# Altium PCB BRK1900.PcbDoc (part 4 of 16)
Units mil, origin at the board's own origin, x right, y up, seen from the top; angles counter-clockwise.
Board outline 8858.27 x 5905.51 mil, 10 copper layers (L1-TOP, L2-GND, L3-PWR, L4-GND, L5-PWR, L6-PWR, L7-GND, L8-SIG, L9-GND, L10-BOT), stack 48.824 mil thick; 456 components, 571 nets, 2296 pads, 2416 vias.
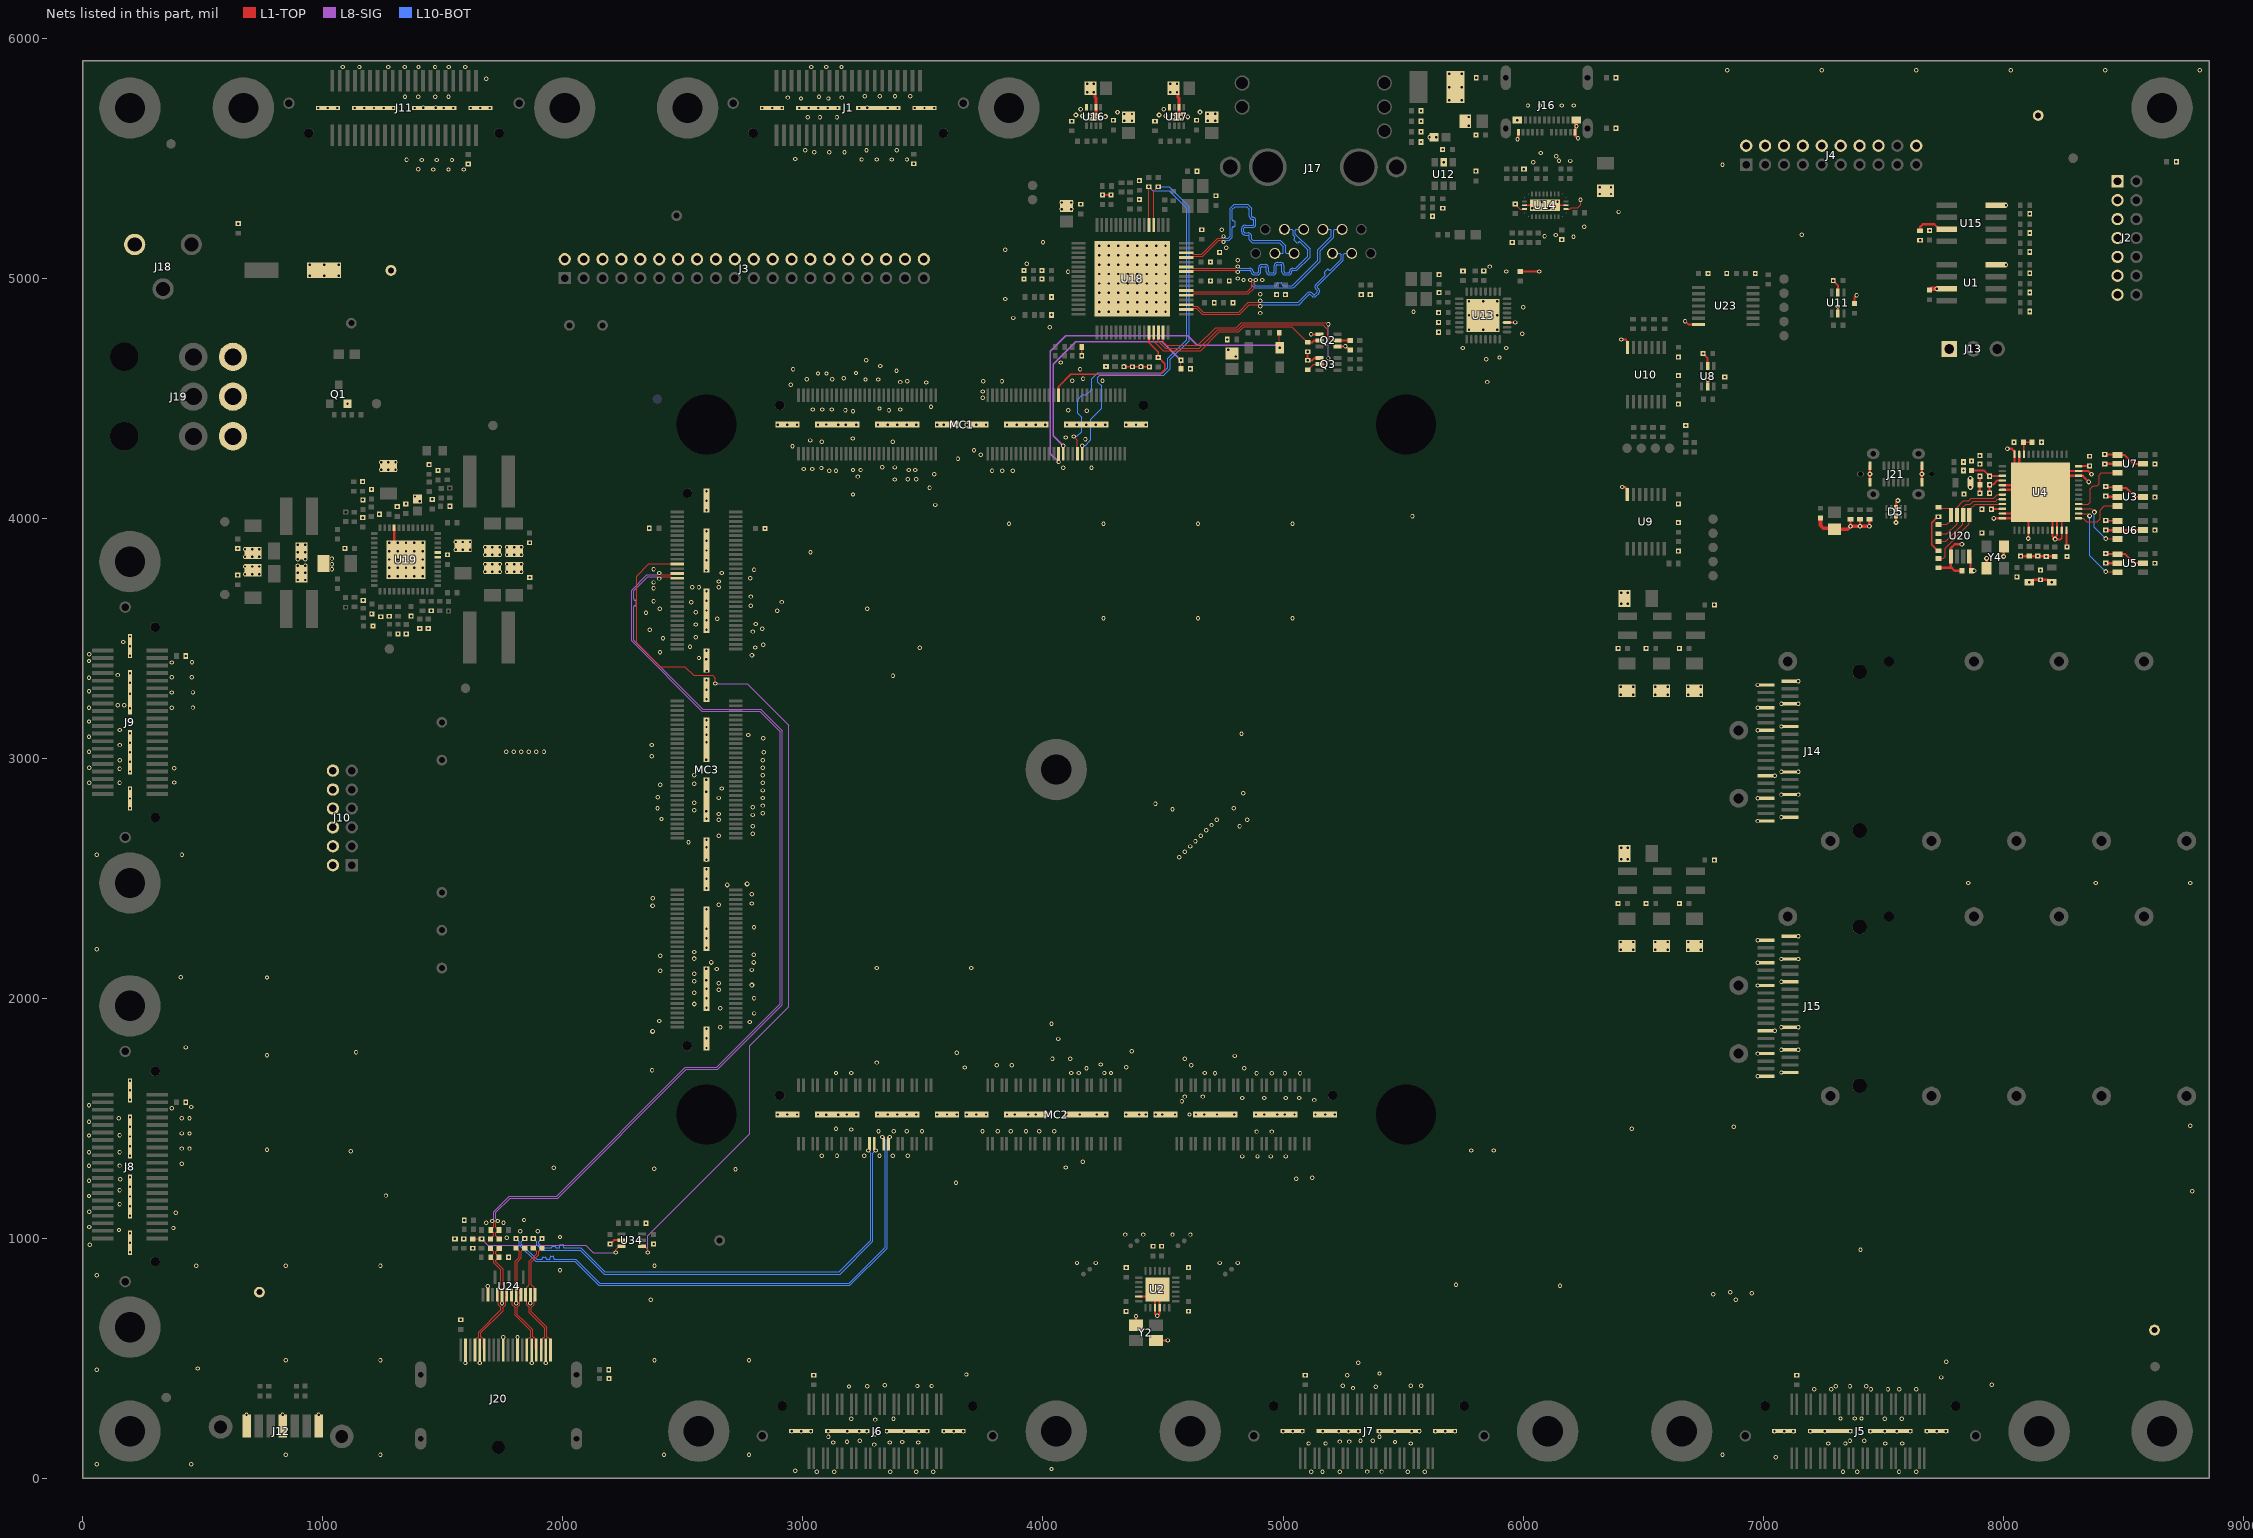
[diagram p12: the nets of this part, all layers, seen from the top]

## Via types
v1: diameter 18, hole 10, L1-TOP to L10-BOT, tented both sides, 2170 vias
v2: diameter 20, hole 10, L1-TOP to L10-BOT, tented both sides, 246 vias

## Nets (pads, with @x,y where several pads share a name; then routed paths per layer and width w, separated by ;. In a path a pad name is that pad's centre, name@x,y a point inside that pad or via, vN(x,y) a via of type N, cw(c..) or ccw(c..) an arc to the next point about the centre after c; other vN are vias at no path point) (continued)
DGND: C1.1 C2.1 C3.1 C4.1 C5.1 C6.1 C7.1 C8.1 C9.1 C10.1 C11.1 C12.1 C13.1 C14.1 C15.1 C16.1 C17.1 C18.1 C19.1 C20.2 C21.2 C22.1 C23.1 C28.1 C29.1 C30.1 C31.1 C32.1 C33.1 C34.1 C35.1 C36.1 C37.1 C38.1 C39.1 C40.1 C41.1 C42.1 C49.1 C50.1 C51.1 C52.1 C53.1 C54.1 C55.1 C56.1 C57.1 C58.1 C59.1 C60.1 C61.1 C62.1 C63.1 C64.1 C65.1 C66.1 C67.1 C68.1 C69.1 C70.1 C71.1 C72.1 C73.1 C74.1 C75.1 C76.1 C77.1 C78.1 C81.1 C82.1 C84.1 C85.1 C86.1 C88.1 C89.1 C90.1 C91.1 C92.1 C93.1 C94.1 C95.1 C96.1 C97.1 C98.1 C99.1 C100.1 C101.1 C102.1 C103.1 C104.1 C105.1 C106.1 C107.1 C108.1 C109.1 C110.1 C111.1 C112.1 C113.1 C114.1 C115.1 C116.2 C117.2 C119.1 C120.1 C121.1 C123.2 C124.2 C125.2 C127.2 C128.2 C129.1 C130.1 C131.1 C132.1 C134.2 C135.1 C136.2 C137.2 C138.2 C140.2 C141.2 C142.1 C143.1 C144.1 C146.2 C147.2 C148.2 C150.1 C151.1 C152.1 C155.2 C156.1 C157.2 C159.1 C163.1 C164.1 C168.2 C178.1 C179.1 C180.1 C181.1 C183.1 C184.1 C186.1 C188.1 C190.1 C212.1 C213.1 C214.2 C215.1 C218.1 C219.1 C220.1 C221.1 D5.3 D5.8 FB1.2 FB5.2 J1.0 J2.1 J2.3 J2.5 J2.7 J2.9 J2.11 J2.13 J3.2 J3.4 J3.6 J3.8 J3.10 J3.12 J3.14 J3.16 J3.18 J3.20 J3.22 J3.24 J3.26 J3.28 J3.30 J3.32 J3.34 J3.36 J3.38 J3.40 J4.2 J4.4 J4.6 J4.8 J4.10 J4.12 J4.14 J4.16 J4.20 J5.0 J6.0 J7.0 J8.0 J9.0 J10.2 J10.4 J10.6 J10.8 J10.10 J10.12 J11.0 J12.1 J12.4 J12.7 J13.1 J14.1 J14.4 J14.7 J14.13 J14.16 J14.19 J14.20 J14.23 J14.26 J14.32 J14.35 J14.38 J15.1 J15.4 J15.7 J15.13 J15.16 J15.19 J15.20 J15.23 J15.26 J15.32 J15.35 J15.38 J16.A1 J16.A12 J16.B1 J16.B12 J18.2 J19.4 J19.5 J19.6 J20.2 J20.5 J20.8 J20.11 J20.16 J20.19 J21.A1 J21.A12 J21.B1 J21.B12 MC1.0 MC2.0 MC3.0 Q1.2 Q2.1 Q2.4 Q3.1 R1.1 R5.1 R6.1 R7.1 R8.1 R11.1 R12.2 R13.1 R14.1 R15.1 R16.1 R17.1 R18.1 R19.2 R20.1 R22.2 R23.2 R24.2 R26.1 R59.1 R61.1 R66.1 R70.2 R73.2 R76.1 R77.2 R78.2 R79.2 R83.1 R87.1 R88.1 R89.1 R90.1 R91.1 R92.1 R93.1 R96.1 R103.1 R105.1 R106.1 R107.1 R108.1 R109.1 R110.1 R112.1 R118.1 R123.1 R126.1 R130.1 R131.2 R134.1 R135.1 R140.1 R152.1 R154.1 R155.1 R156.2 R157.2 R159.1 R169.1 R184.1 TP2.1 TP5.1 TP8.1 TP11.1 U1.4 U1.7 U2.3 U2.4 U2.23 U2.PAD U3.2 U4.4 U4.9 U4.10 U4.11 U4.22 U4.23 U4.35 U4.36 U4.41 U4.42 U4.47 U4.48 U4.PAD U5.2 U6.2 U6.5 U7.2 U8.2 U8.5 U9.7 U10.7 U11.2 U11.5 U12.2 U13.0 U13.11 U14.12 U14.13 U14.28 U14.29 U14.PAD U15.4 U16.2 U16.4 U16.EP U17.2 U17.4 U17.EP U18.PAD U19.7 U19.8 U19.21 U19.PAD U20.5 U23.7 U24.2 U24.5 U24.8 U24.11 U34.2 Y2.2 Y2.4 Y4.2 Y4.4 | length 5547.5
  L1-TOP w5: v1(5967.41,5308.4) 5968,5308.4 5975.74,5300.67 5975.74,5300.07 5988.31,5287.5 U14.29@6005.76,5287.5 ; U14.12@6178.99,5287.5 6194.5,5287.5 6201,5294 6227.22,5294 6239.22,5306 v1(6239.22,5326)
  L1-TOP w7: U13.11@5932.96,4814.94 5966.68,4814.94 v1(5967.02,4815.28)
  L1-TOP w7.5: U14.28@6005.76,5303.24 6091,5303.24 U14.PAD@6091.59,5303.83 6092.18,5303.24 U14.13@6178.99,5303.24
  L1-TOP w8: v1(2196.85,976.38) 2197.44,976.38 2213.58,992.52 U34.2@2244.09,992.52 ; v1(4161.42,4677.17) R92.1@4161.42,4712.6 ; v2(4248.09,5347.15) 4248.03,5347.1 C96.1@4248.03,5346.85 4258.56,5346.85 4258.86,5347.15 ; C96.1@4258.56,5347.15 C95.1@4283.12,5347.15 ; 4270.86,5347.15 4271.16,5346.85 C95.1@4283.46,5346.85 v2(4283.52,5346.76) ; C101.1@4337.21,4630.74 v2(4372.65,4630.74) C91.1@4408.08,4630.74 v2(4443.51,4630.74) ; Y2.2@4387.4,637.8 v1(4387.4,675.59) ; U2.23@4399.61,757.87 4446.85,757.87 U2.PAD@4466.54,777.56 ; Y2.4@4470.87,574.8 v1(4519.69,574.8) ; v1(5102.36,4692.91) v1(5102.36,4657.48) 5122.05,4657.48 5131.89,4667.32 Q3.1@5151.57,4667.32 ; v1(5116.72,4765.94) 5116.81,4765.84 5151.48,4765.84 Q2.1@5151.57,4765.75 ; Q2.4@5226.38,4714.57 5227.36,4715.55 5258.86,4715.55 v1(5259.84,4716.54) 5261.81,4716.54 5269.68,4708.66 5277.56,4700.79 R106.1@5279.53,4700.79 ; R12.2@5988.19,5027.56 v1(6066.93,5027.56) ; v1(6409.28,4744.36) 6426.94,4744.36 6431.62,4739.68 6431.62,4714.08 U10.7@6434.51,4711.19 ; v1(6674.57,4820.59) 6688.18,4806.98 U23.7@6730.74,4806.98 ; v1(6749.82,4685.95) 6749.82,4685.36 6768.9,4666.28 U8.2@6768.9,4634.26 ; U8.5@6768.9,4547.65 v1(6768.94,4575.51) ; v1(7291.94,4989.67) 7291.94,4989.08 7311.02,4970 U11.2@7311.02,4939.98 ; U11.5@7311.02,4853.36 v1(7311.02,4881.89) ; C66.1@7380.02,4893.75 7380.02,4919.67 v1(7389.02,4928.67) ; v2(8104.52,3915.4) 8105.57,3916.45 8105.57,3949.07 U4.4@8105.92,3949.42 U4.PAD@8105.92,4058.68 ; U4.PAD@8155.13,4107.89 U4.PAD@8204.35,4058.68 ; U2.PAD@4466.54,777.56 U2.PAD@4476.38,787.4 4486.22,777.56 U2.4@4486.22,710.63 4486.22,687.01 v1(4476.38,677.17) 4466.54,687.01 U2.3@4466.54,710.63 U2.PAD@4466.54,777.56 ; U4.PAD@8204.35,4058.68 U4.9@8204.35,3949.42 8204.35,3924.25 v2(8215.78,3912.82) ; U4.PAD@8204.35,4058.68 U4.PAD@8224.03,4038.99 ; v2(8215.78,3912.82) 8217.56,3911.04 8237.81,3911.04 8243.72,3916.94 U4.11@8243.72,3949.42 8243.72,4019.31 U4.PAD@8224.03,4038.99 ; v2(8215.78,3912.82) 8218.07,3915.12 8218.07,3923.16 8224.03,3929.12 U4.10@8224.03,3949.42 U4.PAD@8224.03,4038.99
  L1-TOP w10: v1(6413.39,4129.92) 6423.97,4129.92 6434.24,4119.65 U9.7@6434.24,4098.98 ; v2(7363.79,3966.16) R22.2@7363.79,3995.68 ; v2(7403.16,3966.16) R23.2@7403.16,3995.68 ; v2(7442.53,3966.16) R24.2@7442.53,3995.68 ; J21.A12@7444.5,4149.82 J21.B1@7444.5,4217.93 ; D5.8@7552.77,4010.15 7553.07,4009.86 7553.07,3982.26 v2(7553.36,3981.96) ; D5.3@7552.77,4040.17 7553.11,4040.52 7553.11,4062.63 7561.21,4070.73 v2(7561.21,4073.44) ; J21.A1@7661.04,4149.82 J21.B12@7661.04,4217.93 ; R26.1@7729.94,3792.93 7779.15,3792.93 7782.1,3795.88 ; v2(7827.63,3891.07) 7798.17,3891.07 7782.1,3875 U20.5@7782.1,3840.17 7782.1,3795.88 ; C41.1@7827.97,3781.12 7796.87,3781.12 7782.1,3795.88 ; v2(7902.77,4103.95) C22.1@7902.77,4139.39 v2(7902.77,4174.82) ; Y4.2@7929.74,3790.96 7930.72,3791.94 v2(7930.72,3832.3) ; v2(7960.59,3998.98) 7961.16,3999.54 7996.59,3999.54 U4.48@7996.67,3999.62 8046.87,3999.62 U4.PAD@8066.55,4019.31 ; U4.47@7996.67,4019.31 U4.PAD@8066.55,4019.31 ; U4.42@7996.67,4117.73 U4.PAD@8145.29,4117.73 ; U4.41@7996.67,4137.42 U4.PAD@8125.61,4137.42 ; v2(8001.59,3840.17) 8001.59,3880.53 Y4.4@8002.57,3881.51 ; v2(8017.34,4288.99) 8034.9,4288.99 8046.87,4277.02 U4.36@8046.87,4266.35 8046.87,4216.16 U4.PAD@8062.61,4200.41 ; U4.35@8066.55,4266.35 8066.55,4204.35 U4.PAD@8062.61,4200.41 ; v2(8072.46,3841.75) 8073.24,3840.96 8213.4,3840.96 C10.1@8214.19,3840.17 ; v2(8355.92,4151.2) 8330.33,4176.79 U4.22@8313.6,4176.79 U4.PAD@8224.03,4176.79 ; v2(8367.73,4182.69) 8353.95,4196.47 U4.23@8313.6,4196.47 8243.72,4196.47 U4.PAD@8224.03,4176.79 ; v2(8422.85,4225.61) 8423.05,4225.8 8475.8,4225.8 U7.2@8476,4226 ; v2(8426.79,3812.61) U5.2@8476,3812.61 ; v2(8426.79,3950.41) U6.2@8476,3950.41 U6.5@8582.3,3950.41 U6.5@8582.5,3950.21 ; v2(8426.79,4091.75) 8428.56,4089.98 8474.23,4089.98 U3.2@8476,4088.2 ; C34.1@8631.31,3950.21 v2(8631.51,3950.01) ; U4.PAD@8062.61,4200.41 U4.PAD@8125.61,4137.42 ; U4.PAD@8066.55,4019.31 8105.92,4058.68 U4.PAD@8155.13,4107.89 ; U4.PAD@8125.61,4137.42 U4.PAD@8145.29,4117.73 ; U4.PAD@8145.29,4117.73 U4.PAD@8155.13,4107.89 ; U4.PAD@8155.13,4107.89 U4.PAD@8224.03,4176.79
  L1-TOP w11: C157.2@1201.5,3601.56 C157.2@1204.58,3601.56 ; C146.2@1240.7,3589.45 v1(1241.29,3589.45) ; U19.21@1297.37,3959.53 1297.37,3876.85 v1(1346.58,3827.64) ; C156.1@1312.81,3518.08 v1(1313.4,3518.08) ; R134.1@1347.81,3517.87 v1(1348.4,3517.87) ; C124.2@1367.41,3591.92 v1(1368,3591.92) ; C125.2@1402.99,3540.48 v1(1403.58,3540.48) ; v1(5976.48,5578.02) 5980.31,5581.85 J16.A12@5980.31,5607.09 ; J16.A1@6216.17,5602.2 6216.17,5594.75 v1(6228.82,5582.1) ; J16.A1@6216.54,5607.09 6216.54,5654.33 J16.B12@6220.47,5658.27
  L1-TOP w12: U16.EP@4210.63,5672.83 4210.72,5672.83 4220.47,5682.58 U16.2@4220.47,5711.81 4220.47,5749.45 4216.44,5753.48 4216.44,5769.39 4212,5773.83 v2(4211.85,5773.83) ; U17.EP@4557.09,5672.44 4557.18,5672.44 4566.93,5682.19 4566.93,5749.06 4562.9,5753.09 4562.9,5768.99 C86.1@4558.46,5773.43
  L1-TOP w15: C36.1@7238.57,4001.2 7238.57,3970.09 7250.38,3958.28 7293.69,3958.28 FB5.2@7297.62,3954.35 7351.98,3954.35 v2(7363.79,3966.16) v2(7403.16,3966.16) v2(7442.53,3966.16)
  L1-TOP w18: C2.1@7693,4950.08 7693.59,4950.08 7699.51,4956 v1(7722.64,4956) U1.7@7764.64,4956 ; C94.1@7693,5198.08 C94.1@7693.59,5198.08
  L10-BOT w7: v1@1276.58,3754.66 v1(1276.58,3757.64)
  other v1: 3058.17,27.56 3129.92,27.56 3363.33,27.56 3471.55,27.56 3543.31,27.56 5118.11,27.56 5164.47,27.56 5236.22,27.56 5518.8,27.56 5590.55,27.56 7332.68,27.56 7391.73,27.56 7566.04,27.56 7637.8,27.56 5351.31,28.6 5410.36,28.6 2968.5,31.5 4035.43,39.37 59.06,59.06 452.76,59.06 7052.17,87.6 846.46,98.43 1240.16,98.43 2421.26,98.43 2775.59,98.43 6830.71,98.43 3297.61,140.99 5106.3,145.67 5177.17,145.67 5531.5,145.67 7271.65,145.67 7342.52,145.67 7507.87,145.67 7578.74,145.67 3125.98,149.61 3362.2,149.61 3480.32,149.61 3414.3,151.65 5466.33,151.82 3183.78,153.01 5236.22,153.54 5275.59,153.54 3236.22,157.48 5322.83,157.48 5374.02,157.48 7361.32,157.48 7420.37,157.48 3106.3,173.23 5401.57,173.23 3300.52,183.56 2952.88,196.85 2992.88,196.85 3032.88,196.85 3105.38,196.85 3185.38,196.85 3234.15,196.85 3265.38,196.85 3350,197 3421.26,196.85 3482,197 3515.38,196.85 3587.88,196.85 3627.88,196.85 3667.88,196.85 5000.13,196.85 5040.13,196.85 5080.13,196.85 5165.35,196.85 5232.63,196.85 5272.63,196.85 5312.63,196.85 5401.57,196.85 5464.57,196.85 5535.43,196.85 5568,197 5635.13,196.85 5675.13,196.85 5715.13,196.85 7047.24,196.85 7087.35,196.85 7125.98,196.85 7196.85,196.85 7255.91,196.85 7362.2,196.85 7446.85,196.85 7505.91,196.85 7557.09,196.85 7612.2,196.85 7682.28,196.85 7722.39,196.85 7761.02,196.85 3300.68,245.23 7506.99,248.03 7577.85,248.03 3200.94,249.1 3377.42,249.05 7321.95,249.61 7381,249.61 7409.45,249.61 682.48,265.5 832.48,265.5 982.48,265.5 7212.6,371.65 7283.46,371.65 7448.82,371.65 7519.69,371.65 7566.93,371.65 7637.8,371.65 5291.4,376.45 5385.83,381.89 3191.93,382.87 7302.26,383.46 7361.32,383.46 7429.13,383.46 3268.32,384.04 3477,385 3536,385 5248.03,385.83 5532,386.06 5576,386.06 3341,388 7952.76,389.76 2192.08,416 7742.22,420.71 5267.72,429.13 3045,429.69 5093,429.69 7140.24,429.69 3681.1,433.07 5401.57,437.01 59.06,452.76 2191.69,453 479.55,457.99 1594.28,480.95 1653.34,480.95 1869.87,480.95 1928.93,480.95 5312.64,481.56 7762.05,486.16 846.46,492.13 1240.16,492.13 2381.89,492.13 2775.59,492.13 1752.18,588.34 1811.23,588.34 1574.53,661.08 4346.46,696.46 4606.3,696.46 1746.72,729.96 1805.78,729.96 1864.83,729.96 2366.14,744.09 6885.83,744.09 6791.34,767.72 6952.76,771.65 6862.2,775.59 1687.67,800.04 6153.54,803.15 5720.47,807.09 59.06,846.46 1988.19,867.72 4346.46,877.95 4606.3,877.95 472.44,885.83 846.46,885.83 1240.16,885.83 2381.89,885.83 4141.73,897.64 4220.47,897.64 4736.22,897.64 4811.02,897.64 1773.9,922 196.85,941.71 7405.51,952.76 1624.53,958.31 4458.74,966.6 4494.18,966.99 28.71,973.62 2377.95,976.38 196.85,981.71 1550.53,997.69 1587.53,997.69 1766.53,1003 1988.19,1005.51 4342.52,1015.75 4417.32,1015.75 4539.37,1015.75 4614.17,1015.75 196.85,1021.71 1823.09,1029.08 1895.09,1029.08 151,1035 377.95,1043.31 27.05,1047.26 2346.46,1063.39 1681.1,1064.57 1752.95,1064.57 1588.84,1075 1838.58,1076.38 196.85,1094.21 387.2,1106.15 27.05,1110.26 196.85,1134.21 153.54,1141.73 196.85,1174.21 26.07,1176.41 1263.13,1178.3 8787.4,1196.85 153.54,1200.79 196.85,1214.21 3637.8,1232.28 26.07,1239.41 155.96,1246.87 5055.12,1248.03 5122.05,1251.97 196.85,1254.21 2719.41,1288.53 2381.35,1290.51 1961.7,1294.62 4094.49,1295.28 26.07,1302.41 153.54,1303.15 412.01,1311.07 4165.35,1318.9 4830.71,1341.34 4893.7,1341.34 4948.82,1341.34 5011.81,1341.34 196.85,1344.21 3078.74,1343.5 3141.73,1343.5 3255.91,1343.5 3318.9,1343.5 3374.02,1343.5 3437.01,1343.5 153.54,1358.27 26.07,1359.22 1117.13,1362.2 5783.46,1366.14 5877.95,1366.14 767.84,1369.07 412.01,1374.07 444.88,1374 196.85,1384.21 196.85,1424.21 26.07,1428.41 153.54,1429.13 412.01,1437.07 444.88,1437 4889.76,1444.88 4952.76,1444.88 3314.96,1445.67 3377.95,1445.67 3433.07,1445.67 3496.06,1445.67 3748.03,1445.67 3811.02,1445.67 3866.14,1445.67 3929.13,1445.67 3984.25,1445.67 4047.24,1445.67 3200.79,1453.59 3138,1456 6452.76,1456.69 196.85,1464.21 6877.95,1464.57 8779.53,1468.5 26.07,1485.22 149.61,1500 412.01,1500.07 444.88,1500 196.85,1504.21 3097,1515 3148,1515 2895.24,1515.75 2935.24,1515.75 2975.24,1515.75 3062.72,1515.75 3182.72,1515.75 3222.72,1515.75 3312.72,1515.75 3352.72,1515.75 3392.72,1515.75 3432.72,1515.75 3472.72,1515.75 3560.2,1515.75 3600.2,1515.75 3640.2,1515.75 3682.64,1515.75 3722.64,1515.75 3762.64,1515.75 3850.12,1515.75 3883,1516 3938,1516 3970.12,1515.75 4010.12,1515.75 4097,1516 4153.54,1515.75 4224.41,1515.75 4260.12,1515.75 4347.6,1515.75 4401.57,1515.75 4427.6,1515.75 4470.04,1515.75 4496.06,1515.75 4550.04,1515.75 4610.24,1515.75 4637.52,1515.75 4671,1516 4725,1516 4797.52,1515.75 4887.52,1515.75 4921,1516 4976,1516 5007.52,1515.75 5047.52,1515.75 5135,1515.75 5175,1515.75 5215,1515.75 371.18,1542.19 452.76,1547.24 26.07,1554.41 429.69,1567 4578.74,1570.87 5130,1576 196.85,1576.71 4830.71,1584.65 4921.26,1584.65 5011.81,1584.65 5066.93,1584.65 4590.55,1590.55 4665.35,1590.55 196.85,1616.71 196.85,1656.71 6977.14,1675.28 4716.54,1688.19 4889.76,1688.19 4952.76,1688.19 5007.87,1688.19 5070.87,1688.19 3137.8,1688.98 3200.79,1688.98 4118.11,1688.98 4149.61,1688.98 4255.91,1688.98 4283.46,1688.98 4673.23,1688.98 7075.96,1691.03 2371.64,1700.6 4181.1,1708.66 4838.58,1708.66 3674.21,1711.61 4346.46,1712.6 3807.09,1720.47 3870.08,1720.47 4618.11,1720.47 4240.16,1724.41 3307.09,1732.28 4039.37,1748.03 4114.17,1748.03 4590.55,1748.03 4799.21,1759.84 767.84,1762.77 6977.14,1769.77 3640.75,1773.62 1138.78,1775.59 4370.08,1779.53 7075.96,1785.52 7146.89,1785.52 2598.42,1792.87 429.13,1795.28 4062.99,1830.71 2598.42,1832.87 7048.07,1864.26 2598.42,1872.87 2655.37,1879.15 7075.96,1880.01 7146.89,1880.01 4035.43,1893.7 2778.67,1901.21 2401.57,1905.51 2796.57,1936.88 2656.13,1958.52 2598.42,1960.35 2598.42,2000.35 2796.57,2000.03 2547.24,2023.62 2598.42,2040.35 6977.14,2053.24 2649.61,2062.99 7075.96,2068.98 2598,2075 409,2087 767.72,2086.61 2547.24,2102.36 2405.51,2114.17 2787.4,2118.11 2641.73,2122.05 2598,2123 3307.09,2125.98 3700.79,2125.98 6977.14,2147.72 7075.96,2163.47 7146.89,2163.47 2405.51,2177.17 2795.28,2181.1 2547.24,2192.91 6407.07,2201.43 6459.07,2201.43 6549.79,2201.43 6601.79,2201.43 6688.57,2201.43 6740.57,2201.43 59.06,2204.72 2598.42,2210.35 6407.07,2234.35 6459.07,2234.35 6549.79,2234.35 6601.79,2234.35 6688.57,2234.35 6740.57,2234.35 6977.14,2242.21 2598.42,2250.35 7146.89,2257.96 2598.42,2290.35 2796.44,2295.95 2598.42,2370.35 2786.57,2394.67 6395.48,2395.04 6512.4,2394.68 6651.18,2394.68 2374.02,2417.32 2786.57,2434.04 2598.42,2457.83 7854.33,2480.32 8385.83,2480.32 8779.53,2480.32 2598.42,2497.83 2598.42,2537.83 6796.65,2575.79 2598.42,2577 6408.46,2579.72 6436.02,2579.72 4568.28,2587.97 59.06,2598.43 413.39,2598.43 4590.55,2610.24 6408.46,2626.97 6435.63,2626.97 2598.42,2629 4612.82,2632.51 2523.62,2649.61 4635.09,2654.78 2598.42,2660.28 2649.61,2677.17 4657.36,2677.05 2791.34,2685.04 4679.64,2699.32 2791.34,2716.54 4818.9,2716.54 4701.91,2721.59 6977.15,2738.29 2649.61,2744.09 4724.18,2743.86 4850.39,2744.09 2411,2746.73 2598.42,2747.76 7075.97,2754.04 2791.34,2763.78 2649.61,2767.72 2833.29,2771.34 2598,2779 2547.24,2783.46 4539.37,2787.4 2394.28,2791.31 4795.28,2791.34 196.85,2792.11 2791.34,2795.28 2833.29,2802.83 4468.5,2811.02 2547.24,2814.96 196.85,2832.11 6977.15,2832.78 2833.29,2834.33 2649.61,2834.65 2394.85,2837.88 7075.97,2848.53 7146.9,2848.53 4834.65,2854.33 2598,2861 2833.29,2865.83 196.85,2872.11 2661.42,2874.02 2405.51,2889.76 2547.24,2893.7 2833.29,2897.32 27.05,2897.66 153.54,2897.64 381.68,2899.01 2598,2910 7048.08,2927.27 2547.24,2929.13 2833.29,2928.82 7075.97,2943.02 7146.9,2943.02 196.85,2944.61 153.54,2956.69 381.62,2958.8 2833.29,2960.32 27.05,2960.66 196.85,2984.61 153.7,2991.71 2833.29,2991.81 2598,2994 2370.08,3007.87 196.85,3024.61 2837.27,3024.61 26.07,3026.81 1763.78,3027.56 1795.28,3027.56 1826.77,3027.56 1858.27,3027.56 1889.76,3027.56 1921.26,3027.56 153.7,3054.71 2370.08,3055.12 196.85,3064.61 2598.43,3066.93 2834.65,3082.68 26.07,3089.81 2772.16,3096.88 2598.43,3098.43 4826.77,3102.36 196.85,3104.61 6977.15,3116.24 153.7,3117.71 2598.43,3129.92 7075.97,3131.99 26.07,3152.81 2598.42,3157.76 196.85,3208.66 26.07,3209.61 370.31,3210.85 459.14,3211 6977.15,3210.73 145.67,3220.47 173.23,3220.47 7075.97,3226.48 7146.9,3226.48 2598.42,3245.24 6407.07,3264.43 6459.07,3264.43 6549.79,3264.43 6601.79,3264.43 6688.57,3264.43 6740.57,3264.43 197,3268 370.31,3273.85 459.14,3274 26.07,3278.81 2598.42,3285.24 6407.07,3297.35 6459.07,3297.35 6549.79,3297.35 6601.79,3297.35 6688.57,3297.35 6740.57,3297.35 6977.15,3305.22 196.85,3314.61 7146.9,3320.97 2598.42,3325.24 26.07,3335.61 370.6,3337.19 454.75,3336.87 3375,3344 145.67,3346.46 196.85,3354.61 2599,3363 370.48,3398.93 455.2,3400.18 26.07,3404.81 2598,3412 2566.93,3417.32 429.69,3426 196.85,3427.11 27.05,3433.16 2404.76,3441.02 2598.42,3447.68 6395.48,3458.03 6512.4,3457.68 6651.18,3457.68 3486.66,3459.72 2800.91,3461.42 2529.73,3464.47 196.85,3467.11 2834.65,3472.44 169.29,3484.25 2417.32,3500 2553.27,3503.94 196.85,3507.11 2791.34,3527.56 2362.2,3535.43 2598.42,3535.16 2830.71,3539.37 1439.66,3540.56 1209.24,3550.66 2553.27,3557.09 2803.15,3559.06 2598.42,3575.16 2643.58,3580.71 4251.97,3582.68 4645.67,3582.68 5039.37,3582.68 1277.29,3591.84 1203.04,3601.56 2346.46,3606.3 2553.27,3608.27 1451.58,3613.95 2893.7,3614.17 2598.42,3615.16 3267.72,3622.05 2404,3623 2783.25,3635.56 6796.65,3638.78 6408.46,3642.72 6436.02,3642.72 2534.86,3650.29 2911.36,3650.38 2377.95,3653.54 2598.42,3655.16 1169,3657.31 2783.25,3673.29 6408.46,3689.96 6435.63,3689.96 2598.42,3695.16 2377.95,3708.66 2539.37,3712.6 2566.93,3712.6 2649.61,3712.6 2377.95,3732.28 2649.61,3736.22 895.64,3742.42 927.81,3742.42 2780.35,3749.89 1862.58,3752.72 1311.58,3757.64 1346.58,3757.64 1381.58,3757.64 1416.58,3757.64 645.58,3762.8 676.18,3766.64 706.18,3766.64 735.88,3766.64 895.64,3772.42 927.81,3772.42 2661.42,3771.65 1676.58,3776.64 1706.58,3776.64 1736.58,3776.64 1767.58,3776.64 1797.58,3776.64 1827.58,3776.64 2597.63,3781.99 2796.57,3785.43 1038.11,3786.64 2377.95,3787.4 1276.58,3792.64 1311.58,3792.64 1346.58,3792.64 1381.58,3792.64 1416.58,3792.64 676.18,3798.81 706.18,3798.81 735.88,3798.81 895.64,3802.42 927.81,3802.42 1038.11,3808.64 1676.58,3808.81 1706.58,3808.81 1736.58,3808.81 1767.58,3808.81 1797.58,3808.81 1827.58,3808.81 2598.42,3825.16 1276.58,3827.64 1311.58,3827.64 1381.58,3827.64 1416.58,3827.64 895.36,3828.58 927.54,3828.58 1038.11,3831.64 676.18,3838.46 706.18,3838.46 735.88,3838.46 1676.58,3847.46 1706.58,3847.46 1736.58,3847.46 1767.58,3847.46 1797.58,3847.46 1827.58,3847.46 1519.58,3847.72 3031.5,3858.27 895.36,3858.58 927.54,3858.58 1276.58,3862.64 1311.58,3862.64 1346.58,3862.64 1381.58,3862.64 1416.58,3862.64 6646.94,3862.61 2598.42,3865.16 1553.58,3868.64 1583.58,3868.64 1613.58,3868.64 676.18,3870.64 706.18,3870.64 735.88,3870.64 645.58,3873.56 1091.92,3874 1676.58,3879.64 1706.58,3879.64 1736.58,3879.64 1767.58,3879.64 1797.58,3879.64 1827.58,3879.64 895.36,3888.58 927.54,3888.58 1276.58,3897.64 1311.58,3897.64 1346.58,3897.64 1381.58,3897.64 1416.58,3897.64 1861.58,3897.56 1553.58,3900.81 1583.58,3900.81 1613.58,3900.81 2598.42,3905.16 2598.42,3945.16 2842.16,3957 2359.92,3958 3858.27,3976.38 4251.97,3976.38 4645.67,3976.38 5039.37,3976.38 6646.94,3981.5 1166,4002.37 5539,4008.08 1235.92,4016 2598.42,4032.64 1310.58,4047.72 1529.69,4049 3551.18,4055.12 6646.94,4059.46 1346.58,4059.72 1404,4071 2598.42,4072.64 1167,4076.08 1456,4078.08 1384,4090 3208.66,4098.43 2598.42,4112.06 1203,4120.08 3527.56,4125.98 1166,4152.08 3383.18,4160.87 3437.01,4161.42 3472.44,4161.42 3228.35,4173.23 3547.33,4182.7 3110.24,4196.85 3137.8,4196.85 3788,4197 3831,4197 3874.02,4196.85 1480,4199.08 1243,4201 1273,4201 1303,4201 3208.66,4200.79 3240.16,4200.79 3440.94,4200.79 3468.5,4200.79 3003.94,4204.72 3039.37,4204.72 3077.11,4208.75 4085,4210 4202,4210 3382.89,4211.23 3330.53,4211.61 1443,4223.08 1243,4233.17 1273,4233.17 1303,4233.17 3645.67,4248.03 3740.16,4263.78 3712.6,4283.46 2956.69,4299.21 3078.74,4318.9 3374.02,4318.9 3030,4323.74 4176.89,4329.26 3207,4332 4095,4336 6677.17,4385.83 3147,4389 3178,4389 2895.24,4389.76 2935.24,4389.76 2975.24,4389.76 3062.72,4389.76 3097,4390 3222.72,4389.76 3312.72,4389.76 3352.72,4389.76 3392.72,4389.76 3432.72,4389.76 3472.72,4389.76 3560.2,4389.76 3586.61,4389.76 3640.2,4389.76 3682.64,4389.76 3722.64,4389.76 3762.64,4389.76 3850.12,4389.76 3890.12,4389.76 3930.12,4389.76 3970.12,4389.76 4010.12,4389.76 4100.12,4389.76 4140.12,4389.76 4180.12,4389.76 4220.12,4389.76 4260.12,4389.76 4347.6,4389.76 4387.6,4389.76 4427.6,4389.76 3208.66,4444.88 4183,4448 3177.17,4448.82 3358.27,4448.82 4105,4449 3041.19,4452.76 3080.71,4452.76 3120.08,4452.76 3405.51,4452.76 3318.9,4456.69 3533.64,4464.37 6646.59,4474.18 1103.1,4477.3 3749,4502 3749,4527.56 2948.82,4555.12 3514.36,4565.07 3405.51,4566.93 5850.39,4566.93 3751,4570 3829,4570 3435.04,4570.87 4122,4573 4248,4573 3260.9,4577.76 3313.9,4577.76 3015.75,4578.74 3122.05,4578.74 4167,4581 3170.08,4582.66 6839.9,4588.03 6646.59,4593.08 3062.99,4602.36 3098.43,4602.36 3221.27,4604.61 3389.76,4614.17 2959,4619.81 4154.54,4620.06 4614.17,4622.05 3322.83,4633.86 4074.1,4648.32 3263.78,4657.48 5846.46,4661.42 5901.57,4669.29 6646.59,4671.03 4803.15,4673.23 4771.65,4700.79 5748.03,4708.66 5929.13,4708.66 4767.72,4744.09 5996.06,4767.72 5647.94,4774.28 5774.5,4785.41 5833.55,4785.41 5892.61,4785.41 4027.56,4795.28 5647.94,4815.28 3876.18,4833.98 5774.5,4844.46 5833.55,4844.46 5892.61,4844.46 4035.43,4846.46 4905.51,4854.33 5647.94,4856.28 5543.61,4859.16 8110.69,4861 6000,4877.95 4791.73,4897.64 5774.5,4903.52 5833.55,4903.52 5892.61,4903.52 3842.44,4912.87 4035.43,4921.26 4973,4930.92 5010,4930.92 5326,4930.92 5363,4930.92 4905.51,4933.07 5650.02,4939.35 8110.69,4940 4775.98,4988.19 4835.29,4992.18 4913.39,4992.13 3920.87,4996.06 3995.67,4996.06 4811.32,4998.24 945.91,5010 1005.91,5010 1065.91,5010 5650.02,5014.35 6770.9,5019.06 6967.75,5019.06 6848.22,5019.68 8110.69,5020 4104.53,5026.35 5929.13,5027.56 5749.61,5029.09 5836.02,5030.35 3920.87,5031.5 3995.67,5031.5 5860.99,5047.99 945.91,5056 1005.91,5056 1065.91,5056 8011.36,5056 3933.07,5059.06 4811.02,5074.8 4735.83,5107.09 8110.69,5109 3842.52,5118.11 4763.78,5125.98 5954.41,5148.64 4000,5149.61 7653.54,5157.48 6161.35,5159.92 6210,5172 6089.36,5174.88 6136.01,5179.65 7161,5181 8110.69,5188 7693.3,5198.08 4661.42,5200.79 4744.09,5200.79 6255,5214 648,5227.08 5622.69,5257 8110.69,5268 6397.64,5275.59 6038.41,5290.32 6108.41,5290.32 5665.35,5291.34 8011.36,5304 4157.48,5307.48 6075.41,5317.32 6143.41,5317.32 4401.57,5327.17 4720.47,5342.91 6318.9,5350.39 6366.14,5350.39 6318.9,5377.95 6366.14,5377.95 4401.57,5405.91 5803.15,5445.28 1460.64,5452.39 1523.64,5452.39 1586.64,5452.39 1397.64,5452.76 6003.41,5454.01 6830.71,5472.44 1606,5475.31 3462,5476.31 5669.29,5482.28 6042,5482 8720.87,5484.25 6149.61,5488.19 6197,5488 1412,5492 1475,5492 1538,5492 1349,5493 3244.39,5494.14 3307.39,5494.14 3370.39,5494.14 3433.39,5494.14 2968.5,5496.06 6137.8,5507.87 6074,5521 3047.24,5523.62 3110.24,5523.62 3173.23,5523.62 3265,5532 3391,5532 3010,5533 5664.96,5535.43 5574.8,5566.93 5610.24,5586.61 5637.8,5586.61 5803.92,5596 5574.8,5610.24 6386.69,5624 6222.48,5633.1 5773,5635 5574.8,5653.54 5976.38,5658.27 3019.69,5669.29 3070.87,5669.29 3141.73,5669.29 5773,5671 4196.85,5673.23 4228.35,5673.23 4543.31,5672.83 4574.8,5672.83 5574.8,5696.85 981.08,5708.66 1021.08,5708.66 1061.08,5708.66 1133.58,5708.66 1173.58,5708.66 1213.58,5708.66 1253.58,5708.66 1293.58,5708.66 1383.58,5708.66 1418,5709 1470,5709 1503.58,5708.66 1543.58,5708.66 1616.08,5708.66 1656.08,5708.66 1696.08,5708.66 2831.48,5708.66 2871.48,5708.66 2911.48,5708.66 2983.98,5708.66 3023.98,5708.66 3063.98,5708.66 3103.98,5708.66 3143.98,5708.66 3233.98,5708.66 3268,5709 3353.98,5708.66 3393.98,5708.66 3466.48,5708.66 3506.48,5708.66 3546.48,5708.66 6020,5719 6070,5719 6161,5719 6211,5719 5692.91,5740.16 5744.09,5740.16 2992.13,5748.03 3106.3,5748.03 2937.01,5751.97 3161.42,5751.97 1342.52,5755.91 1397.75,5755.91 1468.52,5755.91 1523.75,5755.91 3066.93,5755.91 3257.62,5757.52 3320.62,5757.52 3383.62,5757.52 3446.62,5757.52 5692.91,5795.28 5744.09,5795.28 1681.1,5830.71 5804.31,5834 6386.69,5834 5692.91,5850.39 5744.09,5850.39 6850.39,5866.14 7244.09,5866.14 7637.8,5866.14 8031.5,5866.14 8425.2,5866.14 8818.9,5866.14 1083.59,5879.44 1152.78,5879.44 1272.59,5879.44 1341.78,5879.44 1398.59,5879.44 1467.78,5879.44 1524.59,5879.44 1593.78,5879.44 3034.68,5879.44 3097.68,5879.44 3160.68,5879.44
  other v2: 2374.02,1862.2 2547.24,1976.38 2649.61,2035.43 2787.4,2055.12 2547.24,2070.87 2618.11,2149.61 2795.28,2149.61 2547.24,2165.35 2374.02,2385.83 2649.61,2389.76 2685.04,2472.44 2767.72,2476.38 2787.4,3429.13 8056.71,3755.13 8155.13,3783.48 8631.51,3812.22 8178.76,3840.17 8265.37,3840.17 8143.32,3842.53 7910.64,3938.6 7910.64,4037.02 8631.51,4087.81 7836.63,4100.01 7444.5,4183.87 7661.04,4183.87 7834.27,4198.44 7902.77,4225.01 8631.51,4225.61 7834.27,4233.87 7867.73,4238.2 8359.86,4257.89 7902.77,4260.45 8159.46,4316.55 4337.21,4631.14 4408.08,4631.14 4262.72,4631.84 4234.85,4859.48 4274.22,4859.48 4313.59,4859.48 4352.96,4859.48 4392.33,4859.48 4431.7,4859.48 4471.07,4859.48 4510.44,4859.48 4713.39,4897.64 4234.85,4898.85 4274.22,4898.85 4313.59,4898.85 4352.96,4898.85 4392.33,4898.85 4431.7,4898.85 4471.07,4898.85 4510.44,4898.85 4234.85,4938.22 4274.22,4938.22 4313.59,4938.22 4352.96,4938.22 4392.33,4938.22 4431.7,4938.22 4471.07,4938.22 4510.44,4938.22 4234.85,4977.59 4274.22,4977.59 4313.59,4977.59 4352.96,4977.59 4392.33,4977.59 4431.7,4977.59 4471.07,4977.59 4510.44,4977.59 4697.64,4988.19 4234.85,5016.96 4274.22,5016.96 4313.59,5016.96 4352.96,5016.96 4392.33,5016.96 4431.7,5016.96 4471.07,5016.96 4510.44,5016.96 4234.85,5056.33 4274.22,5056.33 4313.59,5056.33 4352.96,5056.33 4392.33,5056.33 4431.7,5056.33 4471.07,5056.33 4510.44,5056.33 4697.64,5066.93 4234.85,5095.7 4274.22,5095.7 4313.59,5095.7 4352.96,5095.7 4392.33,5095.7 4431.7,5095.7 4471.07,5095.7 4510.44,5095.7 4234.85,5135.07 4274.22,5135.07 4313.59,5135.07 4352.96,5135.07 4392.33,5135.07 4431.7,5135.07 4471.07,5135.07 4510.44,5135.07 4078.74,5287.4 4118.11,5287.4 4078.74,5314.96 4118.11,5314.96 4641.73,5444.88 4120.08,5653.15 4466.54,5653.15 4339.18,5655.87 4370.68,5655.87 4685.64,5655.87 4717.13,5655.87 4293.31,5657.09 4639.76,5657.48 4602.96,5671.62 4259.84,5672.83 4164.6,5675.4 4511.15,5675.4 4137.04,5679.34 4483.59,5679.34 4339.18,5683.43 4370.68,5683.43 4685.64,5683.43 4717.72,5684.65 4310.27,5691.15 4654.14,5691.3 4156.73,5702.96 4503.28,5702.96 4184.29,5773.83 4530.84,5773.83 4558.4,5773.83 4184.29,5809.26 4211.85,5809.26 4530.84,5809.26 4558.4,5809.26
DISPLAYPORT_PS_SRC_AUX_N: C171.1 J20.17 R167.1 U24.4 | length 510.7
  L1-TOP w3.3: J20.17@1633.86,534.65 1637.72,538.51 1637.72,580.98 1645.28,588.54 1647.11,588.54 1649.04,590.47 1649.04,600.58 1649.04,609.75 1742.22,702.93 1742.22,712.38 1740.29,714.31 ; C171.1@1698.53,957.92 1712.53,943.92 1712.53,935 R167.1@1699.53,922 1712.53,909 1712.53,898.27 1742.22,868.58 1742.22,842.12 1742.22,806.66 1731.29,795.74 1731.29,769.26 U24.4@1727.04,765 1731.07,760.96 1731.07,723.48 1740.24,714.31
DISPLAYPORT_PS_SRC_AUX_N_C: C171.2 MC3.153 R158.1 | length 4073.5
  L1-TOP w3.3: v1(1705.53,1072.44) 1705.53,1071.57 1712.53,1064.57 1712.53,1057.47 1712.53,1047.09 1710.59,1045.16 1708.41,1045.16 1700.21,1036.97 R158.1@1700.21,1035 ; 1712.53,1012.08 C171.2@1698.53,998.08 1699.12,998.08 1712.53,1011.49 1712.53,1022.91 1710.59,1024.84 1710.37,1024.84 ; 1712.53,1022.69 1710.37,1024.84 ; v1(2401.57,3771.34) 2403.86,3771.34 2410.86,3764.34 2448.79,3764.34 2454.13,3769.69 MC3.153@2476.77,3769.69 ; R158.1@1700.21,1035 1710.37,1024.84 ; R158.1@1700.21,1035 1700.21,1033.03 1708.41,1024.84 1710.37,1024.84
  L8-SIG w3.15: v1(1705.53,1072.44) 1705.53,1074.71 1712.53,1081.71 1712.53,1111.6 1776.85,1175.93 1974.22,1175.93 2510.89,1712.6 2641.73,1712.6 2905.51,1976.38 2905.51,3110.24 2897.64,3118.11 2820.02,3195.72 2578.95,3195.72 2286.28,3488.4 2286.28,3700.58 2350.04,3764.34 2392.3,3764.34 2399.3,3771.34 v1(2401.57,3771.34)
DISPLAYPORT_PS_SRC_AUX_P: C170.1 J20.15 R154.2 U24.6 | length 510.7
  L1-TOP w3.3: J20.15@1673.23,534.65 1669.37,538.51 1669.37,580.98 1661.81,588.54 1659.98,588.54 1658.04,590.47 1658.04,596.86 1658.04,606.02 1751.22,699.2 1751.22,712.38 1753.16,714.31 ; C170.1@1735.53,957.92 1721.53,943.92 1721.53,935 R154.2@1734.53,922 1721.53,909 1721.53,902 1751.22,872.3 1751.22,838.39 1751.22,806.85 1762.15,795.92 1762.15,769.26 U24.6@1766.41,765 1762.37,760.96 1762.37,723.48 1753.21,714.31
DISPLAYPORT_PS_SRC_AUX_P_C: C170.2 MC3.151 R153.2 | length 4035.6
  L1-TOP w3.3: v1(1728.53,1072.44) 1728.53,1071.57 1721.53,1064.57 1721.53,1053.74 1721.53,1047.09 1723.46,1045.16 1725.65,1045.16 1733.84,1036.97 R153.2@1733.84,1035 1733.84,1033.03 1725.65,1024.84 1723.46,1024.84 1721.53,1022.91 1721.53,1011.49 1734.94,998.08 C170.2@1735.53,998.08 ; v1(2401.57,3748.34) 2403.86,3748.34 2410.86,3755.34 2448.79,3755.34 2454.13,3750 MC3.151@2476.77,3750
  L8-SIG w3.15: v1(1728.53,1072.44) 1728.53,1074.71 1721.53,1081.71 1721.53,1107.87 1780.58,1166.93 1977.95,1166.93 2514.62,1703.6 2645.46,1703.6 2914.51,1972.65 2914.51,3113.96 2823.75,3204.72 2582.68,3204.72 2295.28,3492.13 2295.28,3606.3 2295.28,3631.02 cw(c2299.91,3631.02) 2299.91,3635.65 2301.76,3635.65 ccw(c2301.76,3640.28) 2306.39,3640.28 2306.39,3654.17 ccw(c2301.76,3654.17) 2301.76,3658.8 2299.91,3658.8 cw(c2299.91,3663.43) 2295.28,3663.43 2295.28,3685.04 2295.28,3696.85 2353.77,3755.34 2392.3,3755.34 2399.3,3748.34 v1(2401.57,3748.34)
DISPLAYPORT_PS_SRC_CONN_LANE0_N: C185.1 J20.3 U24.10 | length 489
  L1-TOP w3.3: 1858.35,714.31 1849.18,723.48 1849.18,760.96 U24.10@1845.15,765 1849.41,769.26 1849.41,795.74 1860.33,806.66 1860.33,904.73 1890.59,934.99 1890.59,945.42 C185.1@1877.09,958.92 ; 1858.4,714.31 1860.33,712.38 1860.33,690.85 1893.7,657.48 1924.63,626.55 1924.63,595.14 1924.63,590.47 1922.7,588.54 1920.87,588.54 1913.31,580.98 1913.31,538.51 J20.3@1909.45,534.65
DISPLAYPORT_PS_SRC_CONN_LANE0_P: C182.1 J20.1 U24.12 | length 511.9
  L1-TOP w3.3: 1871.27,714.31 1869.33,712.38 1869.33,694.57 1893.7,670.21 1933.63,630.28 1933.63,598.87 1933.63,590.47 1935.57,588.54 1937.4,588.54 1944.96,580.98 1944.96,538.51 J20.1@1948.82,534.65 ; 1871.32,714.31 1880.48,723.48 1880.48,760.96 U24.12@1884.52,765 ; U24.12@1884.52,742.13 U24.12@1884.52,765 ; C182.1@1913.09,958.92 1899.59,945.42 1899.59,931.26 1869.33,901 1869.33,806.85 1880.26,795.92 1880.26,769.26 U24.12@1884.52,765
DISPLAYPORT_PS_SRC_CONN_LANE1_N: C189.1 J20.6 U24.7 | length 483.6
  L1-TOP w3.3: 1799.3,714.31 1790.13,723.48 1790.13,760.96 U24.7@1786.09,765 1790.35,769.26 1790.35,795.74 1801.28,806.66 1801.28,904.73 1818.59,922.04 1818.59,945.42 C189.1@1805.09,958.92 ; 1799.35,714.31 1801.28,712.38 1801.28,679.04 1838.58,641.73 1865.58,614.74 1865.58,590.47 1863.65,588.54 1861.81,588.54 1854.26,580.98 1854.26,538.51 J20.6@1850.39,534.65
DISPLAYPORT_PS_SRC_CONN_LANE1_P: C187.1 J20.4 U24.9 | length 483.6
  L1-TOP w3.3: 1812.21,714.31 1810.28,712.38 1810.28,682.76 1838.58,654.46 1874.58,618.46 1874.58,590.47 1876.51,588.54 1878.35,588.54 1885.9,580.98 1885.9,538.51 J20.4@1889.76,534.65 ; 1812.26,714.31 1821.43,723.48 1821.43,760.96 U24.9@1825.46,765 1821.21,769.26 1821.21,795.92 1810.28,806.85 1810.28,901 1827.59,918.32 1827.59,945.42 C187.1@1841.09,958.92
DISPLAYPORT_PS_SRC_HPD: MC3.157 U34.4 | length 3739.6
  L1-TOP w5: U34.4@2330.71,966.93 2340.55,966.93 2354.33,953.15 v1(2354.33,940.94) ; MC3.157@2476.77,3809.06 2358.06,3809.06 2307.09,3758.09 2307.09,3480.32 2405.51,3381.89 2507.87,3381.89 2544.91,3344.85 2623.65,3344.85 2634.81,3333.69 2634.81,3311.73 v1(2634.3,3311.22)
  L8-SIG w5: v1(2354.33,940.94) 2354.33,1010.33 2779,1435 2779,1802.62 2940.94,1964.57 2940.94,3137.8 2767.52,3311.22 v1(2634.3,3311.22)
DISPLAYPORT_PS_SRC_HPD_3V3: R159.2 R181.1 U34.3 | length 661
  L1-TOP w5: R159.2@1624.53,997.68 v1(1661.53,997.69) ; v1(2220.47,940.94) 2220.47,953.15 2234.25,966.93 U34.3@2244.09,966.93
  L8-SIG w5: v1(1661.53,997.69) 1688.21,971 2095.93,971 2125.98,940.94 v1(2220.47,940.94)
DISPLAYPORT_PS_SRC_LANE0_N: C185.2 MC2.24 | length 1922.9
  L10-BOT w3.3: v1(1877.09,999.08) 1890.59,985.58 1890.59,973.27 1912.87,951 2023.54,951 2071.7,951 2171.71,851 2181.1,851 3155.07,851 3291.9,987.83 3291.9,1354.85 v1(3303.15,1366.09)
DISPLAYPORT_PS_SRC_LANE0_P: C182.2 MC2.22 | length 1922.9
  L10-BOT w3.3: v1(1913.09,999.08) 1899.59,985.58 1899.59,977 1916.59,960 1940.82,960 1950.59,960 ccw(c1950.59,963.3) 1953.89,963.3 cw(c1957.15,963.3) 1957.15,966.56 1966.93,966.56 cw(c1966.93,963.3) 1970.19,963.3 ; 1970.19,963.26 ccw(c1973.45,963.26) 1973.45,960 1983.23,960 ccw(c1983.23,963.26) 1986.49,963.26 1986.49,970.7 cw(c1989.75,970.7) 1989.75,973.96 1999.53,973.96 cw(c1999.53,970.7) 2002.79,970.7 2002.79,963.3 ccw(c2006.09,963.3) 2006.09,960 2024.04,960 2075.43,960 2175.43,860 2181.1,860 3151.34,860 3282.9,991.56 3282.9,1354.85 v1(3271.65,1366.09)
DISPLAYPORT_PS_SRC_LANE1_N: C189.2 MC2.28 | length 2166.4
  L10-BOT w3.3: v1(1805.09,999.08) 1818.59,985.58 1818.59,972.27 1886.87,904 1980.32,904 2050.09,904 2150.09,804 2181.1,804 2878.73,804 3195.88,804 3350.96,959.07 3350.96,1410.85 v1(3362.2,1422.09)
DISPLAYPORT_PS_SRC_LANE1_P: C187.2 MC2.26 | length 2166.4
  L10-BOT w3.3: v1(1841.09,999.08) 1827.59,985.58 1827.59,976 1890.59,913 1897.9,913 1910.9,913 ccw(c1910.9,916.3) 1914.2,916.3 1914.2,917.65 cw(c1917.46,917.65) 1917.46,920.91 1927.24,920.91 cw(c1927.24,917.65) 1930.5,917.65 1930.5,916.26 ccw(c1933.76,916.26) 1933.76,913 1943.54,913 ccw(c1943.54,916.26) 1946.8,916.26 1946.8,922.35 cw(c1950.06,922.35) 1950.06,925.61 1959.84,925.61 cw(c1959.84,922.35) 1963.1,922.35 1963.1,916.3 ccw(c1966.4,916.3) 1966.4,913 1984.35,913 2053.82,913 2153.82,813 2181.1,813 3192.15,813 3341.96,962.8 3341.96,1410.85 v1(3330.71,1422.09)
EECLK: R25.1 U4.44 U20.2 | length 382.1
  L1-TOP w4.96: R25.1@7729.94,3903.16 7761.43,3903.16 7832.3,3974.03 U20.2@7832.3,4014.39 ; U20.2@7833.28,4013.4 U20.2@7832.3,4014.39 ; U4.44@7996.67,4078.36 7975.88,4078.36 7967.82,4070.3 7875.15,4070.3 7862.62,4057.77 7845.3,4057.77 7832.3,4044.77 U20.2@7832.3,4014.39
EECS: R26.2 U4.45 U20.1 | length 415.2
  L1-TOP w4.96: R26.2@7729.94,3832.3 7749.62,3832.3 7757.5,3840.17 7757.5,3875.61 7858.87,3976.98 U20.1@7858.87,4013.4 7865.25,4019.78 7865.25,4041.24 7882.69,4058.68 U4.45@7996.67,4058.68
EEDATA: R27.1 U4.43 U20.3 | length 374.8
  L1-TOP w4.96: R27.1@7729.94,3934.66 7765.26,3934.66 7807.69,3977.09 U20.3@7807.69,4013.4 7807.69,4046.11 7833.35,4071.77 7856.6,4071.77 7867.34,4082.51 7960.46,4082.51 7976,4098.05 U4.43@7996.67,4098.05
EEPROM_DO: R27.2 R28.1 U20.4 | length 158.5
  L1-TOP w4.96: R27.2@7729.94,3974.03 7765.37,3974.03 7776.24,3984.9 7776.24,4007.54 U20.4@7782.1,4013.4 7782.1,4033.09 7773.24,4041.94 7732.89,4041.94 R28.1@7729.94,4044.9
EEPROM_WP: R93.2 U15.7 | length 140.2
  L1-TOP w10: R93.2@7653.54,5196.85 7653.54,5212.6 7665.35,5224.41 7712.73,5224.41 7733.14,5204 U15.7@7764.64,5204
ETH_1000_LINK: Q2.5 R106.2 U18.62 | length 931.2
  L1-TOP w5: U18.62@4480.91,4772.87 4480.91,4736.1 4508.35,4708.66 4651.52,4708.66 4727.66,4784.81 4810.85,4784.81 4831.37,4805.32 5165.36,4805.32 5185.79,4784.89 5185.79,4755.15 5200.79,4740.16 Q2.5@5226.38,4740.16
  L1-TOP w8: Q2.5@5226.38,4740.16 R106.2@5279.53,4740.16
ETH_ACT: Q2.2 R103.2 U18.61 | length 814.3
  L1-TOP w5: U18.61@4461.23,4772.87 4461.23,4736.12 4500.32,4697.03 4656.73,4697.03 4735.29,4775.59 4814.96,4775.59 4835.77,4796.4 5036.28,4796.4 5100.39,4732.28 R103.2@5102.36,4732.28
  L1-TOP w8: R103.2@5102.36,4732.28 5122.05,4732.28 5129.92,4740.16 Q2.2@5151.57,4740.16
ETH_LINK: Q3.2 R112.2 U18.63 | length 1028.5
  L1-TOP w5: U18.63@4500.6,4772.87 4500.6,4735.83 4515.96,4720.47 4645.67,4720.47 4719.16,4793.97 4805.88,4793.97 4826.22,4814.32 5179.94,4814.32 5187.17,4807.09 v1(5188.98,4807.09) ; R112.2@5102.36,4618.11 5104.33,4618.11 5127.95,4641.73 Q3.2@5151.57,4641.73 5160.43,4641.73 5177.17,4641.73 5188.98,4653.54 v1(5188.98,4665.35)
  L8-SIG w5: v1(5188.98,4665.35) v1(5188.98,4807.09)
ETH_TXRX_A_N: J17.10 U18.3 | length 864.5
  L1-TOP w3.3: U18.3@4597.06,4889.01 4620.68,4889.01 4626.02,4883.67 4642.3,4883.67 4667.7,4858.27 4814.96,4858.27 4855.46,4898.76 4903.58,4898.76 4903.58,4903.83 v1(4905.51,4905.76)
  L10-BOT w3.3: v1(4905.51,4905.76) 4907.8,4905.76 4914.8,4898.76 5062.76,4898.76 5085.94,4921.94 5101.01,4937.01 cw(c5110.67,4927.35) 5118.8,4938.33 5119.01,4938.33 5123.48,4933.87 5125.49,4931.86 ccw(c5128.78,4935.16) 5132.08,4931.86 5141.96,4941.75 ccw(c5138.67,4945.04) 5141.94,4948.36 5136.83,4953.46 ; 5136.83,4953.47 cw(c5146.47,4963.15) 5136.81,4972.81 5141.16,4977.16 5173.21,5009.21 5174.38,5010.38 ccw(c5171.08,5013.67) 5174.38,5016.97 5172.87,5018.48 cw(c5176.16,5021.77) 5172.87,5025.07 5182.75,5034.95 cw(c5186.05,5031.66) 5189.34,5034.95 5190.85,5033.44 ccw(c5194.15,5036.74) 5197.44,5033.44 5207.98,5043.98 5241.5,5077.5 5241.5,5097 5235.9,5102.6 J17.10@5206,5102.6
ETH_TXRX_A_P: J17.11 U18.2 | length 864.5
  L1-TOP w3.3: U18.2@4597.06,4869.33 4620.68,4869.33 4626.02,4874.67 4638.57,4874.67 4663.97,4849.27 4818.69,4849.27 4859.18,4889.76 4903.58,4889.76 4903.58,4884.7 v1(4905.51,4882.76)
  L10-BOT w3.3: v1(4905.51,4882.76) 4907.8,4882.76 4914.8,4889.76 5066.49,4889.76 5092.3,4915.57 5107.38,4930.65 cw(c5110.67,4927.35) 5113.98,4930.64 5119.12,4925.5 ccw(c5128.78,4935.16) 5138.44,4925.5 5148.32,4935.38 ccw(c5138.67,4945.04) 5148.32,4954.7 5146.32,4956.71 5143.16,4959.86 cw(c5146.47,4963.15) 5143.17,4966.44 5147.52,4970.79 5250.5,5073.77 5250.5,5097 5256.1,5102.6 J17.11@5286,5102.6
ETH_TXRX_B_N: J17.5 U18.6 | length 863.9
  L1-TOP w3.3: U18.6@4597.06,4948.07 4620.68,4948.07 4626.02,4942.72 4645.77,4942.72 4851.26,4942.72 4870.08,4961.55 4870.08,4984.06 4863.08,4991.06 v1(4863.08,4992.13)
  L10-BOT w3.3: v1(4863.08,4992.13) 4863.08,4989.84 4870.08,4982.84 4870.08,4970.75 4881.51,4959.32 5043.04,4959.32 5045.68,4961.95 5154,5070.27 5154,5113.27 5210.5,5169.77 5210.5,5198 5215.1,5202.6 J17.5@5246,5202.6
ETH_TXRX_B_P: J17.4 U18.5 | length 863.9
  L1-TOP w3.3: U18.5@4597.06,4928.38 4620.68,4928.38 4626.02,4933.72 4642.04,4933.72 4854.98,4933.72 4879.08,4957.82 4879.08,4984.06 4886.08,4991.06 v1(4886.08,4992.13)
  L10-BOT w3.3: v1(4886.08,4992.13) 4886.08,4989.84 4879.08,4982.84 4879.08,4974.48 4885.24,4968.32 4944.88,4968.32 4968.93,4968.32 ccw(c4968.93,4972.98) 4973.59,4972.98 4973.59,4975.11 cw(c4978.25,4975.11) 4978.25,4979.77 4992.23,4979.77 cw(c4992.23,4975.11) 4996.89,4975.11 4996.89,4972.98 ccw(c5001.55,4972.98) 5001.55,4968.32 5026.5,4968.32 5039.32,4968.32 5145,5074 5145,5117 5201.5,5173.5 5201.5,5198 5196.9,5202.6 J17.4@5166,5202.6
ETH_TXRX_C_N: J17.2 U18.11 | length 863.9
  L1-TOP w3.3: U18.11@4597.06,5046.49 4620.68,5046.49 4626.02,5041.15 4645.77,5041.15 4801.74,5041.15 4808.74,5048.15 v1(4811.02,5048.15)
  L10-BOT w3.3: v1(4811.02,5048.15) 4813.31,5048.15 4820.31,5041.15 4838.58,5041.15 4861.27,5041.15 cw(c4861.27,5027.49) 4874.93,5027.49 ccw(c4879.59,5027.49) 4879.59,5022.83 4893.57,5022.83 ccw(c4893.57,5027.49) 4898.23,5027.49 4898.23,5042.99 cw(c4911.89,5042.99) 4911.89,5056.65 4925.87,5056.65 cw(c4925.87,5042.99) 4939.53,5042.99 4939.53,5026.87 ccw(c4944.19,5026.87) 4944.19,5022.21 4958.17,5022.21 ccw(c4958.17,5026.87) 4962.83,5026.87 4962.83,5051.29 cw(c4976.49,5051.29) 4976.49,5064.95 4990.47,5064.95 cw(c4990.47,5051.29) 5004.13,5051.29 5004.13,5026.87 ccw(c5008.79,5026.87) 5008.79,5022.21 5022.77,5022.21 ccw(c5022.77,5026.87) 5027.43,5026.87 5027.43,5027.49 cw(c5041.09,5027.49) 5041.09,5041.15 5047.24,5041.15 5053.82,5041.15 5103.39,5090.71 5103.39,5117.56 5072.56,5148.39 5071.39,5149.56 ccw(c5068.1,5146.26) 5064.8,5149.56 5063.29,5148.04 cw(c5060,5151.34) 5056.7,5148.04 5046.82,5157.93 cw(c5050.11,5161.23) 5046.82,5164.52 5048.33,5166.03 ccw(c5045.03,5169.33) 5048.33,5172.62 5043.77,5177.18 5041.5,5179.45 5041.5,5198 5036.9,5202.6 J17.2@5006,5202.6
ETH_TXRX_C_P: J17.3 U18.10 | length 863.9
  L1-TOP w3.3: U18.10@4597.06,5026.81 4620.68,5026.81 4626.02,5032.15 4642.04,5032.15 4801.74,5032.15 4808.74,5025.15 v1(4811.02,5025.15)
  L10-BOT w3.3: v1(4811.02,5025.15) 4813.31,5025.15 4820.31,5032.15 4838.58,5032.15 4861.27,5032.15 cw(c4861.27,5027.49) 4865.93,5027.49 ccw(c4879.59,5027.49) 4879.59,5013.83 4893.57,5013.83 ccw(c4893.57,5027.49) 4907.23,5027.49 4907.23,5042.99 cw(c4911.89,5042.99) 4911.89,5047.65 4925.87,5047.65 cw(c4925.87,5042.99) 4930.53,5042.99 4930.53,5026.87 ccw(c4944.19,5026.87) 4944.19,5013.21 4958.17,5013.21 ccw(c4958.17,5026.87) 4971.83,5026.87 4971.83,5051.29 cw(c4976.49,5051.29) 4976.49,5055.95 4990.47,5055.95 cw(c4990.47,5051.29) 4995.13,5051.29 4995.13,5026.87 ccw(c5008.79,5026.87) 5008.79,5013.21 5022.77,5013.21 ccw(c5022.77,5026.87) 5036.43,5026.87 5036.43,5027.49 cw(c5041.09,5027.49) 5041.09,5032.15 5047.24,5032.15 5057.55,5032.15 5112.39,5086.99 5112.39,5121.29 5050.5,5183.18 5050.5,5198 5055.1,5202.6 J17.3@5086,5202.6
ETH_TXRX_D_N: J17.9 U18.14 | length 863.9
  L1-TOP w3.3: U18.14@4597.06,5105.55 4620.68,5105.55 4626.02,5100.2 4644.48,5100.2 4661.84,5100.2 4728.11,5166.48 4743.91,5166.48 4750.91,5173.48 v1(4751.97,5173.48)
  L10-BOT w3.3: v1(4751.97,5173.48) 4754.25,5173.48 4761.25,5166.48 4771.65,5166.48 4780,5174.83 4780,5290.25 4796.86,5307.11 4852.98,5307.11 4869,5291.09 4869,5279.49 4869,5257.53 ccw(c4873.66,5257.53) 4873.66,5252.87 cw(c4873.66,5239.21) 4887.32,5239.21 4887.32,5225.23 cw(c4873.66,5225.23) 4873.66,5211.57 4841.64,5211.57 ccw(c4841.64,5206.91) 4836.98,5206.91 4836.98,5192.93 ccw(c4841.64,5192.93) 4841.64,5188.27 4855.34,5188.27 cw(c4855.34,5174.61) 4869,5174.61 4869,5168.46 4869,5162.5 4874.5,5157 4987.73,5157 5010.5,5134.23 5010.5,5106 5013.9,5102.6 J17.9@5046,5102.6
ETH_TXRX_D_P: J17.8 U18.13 | length 863.9
  L1-TOP w3.3: U18.13@4597.06,5085.86 4620.68,5085.86 4626.02,5091.2 4640.75,5091.2 4665.56,5091.2 4731.84,5157.48 4743.91,5157.48 4750.91,5150.48 v1(4751.97,5150.48)
  L10-BOT w3.3: v1(4751.97,5150.48) 4754.25,5150.48 4761.25,5157.48 4775.38,5157.48 4789,5171.1 4789,5185.04 4789,5209.99 cw(c4793.66,5209.99) 4793.66,5214.65 4795.8,5214.65 ccw(c4795.8,5219.31) 4800.46,5219.31 4800.46,5233.29 ccw(c4795.8,5233.29) 4795.8,5237.95 4793.66,5237.95 cw(c4793.66,5242.61) 4789,5242.61 4789,5264.04 4789,5286.52 4800.58,5298.11 4849.25,5298.11 4860,5287.36 4860,5279.49 4860,5257.53 ccw(c4873.66,5257.53) 4873.66,5243.87 cw(c4873.66,5239.21) 4878.32,5239.21 4878.32,5225.23 cw(c4873.66,5225.23) 4873.66,5220.57 4841.64,5220.57 ccw(c4841.64,5206.91) 4827.98,5206.91 4827.98,5192.93 ccw(c4841.64,5192.93) 4841.64,5179.27 4855.34,5179.27 cw(c4855.34,5174.61) 4860,5174.61 4860,5168.46 4860,5158.77 4870.77,5148 4984,5148 5001.5,5130.5 5001.5,5106 4998.1,5102.6 J17.8@4966,5102.6
FT232_RESET: C35.2 R21.1 U4.34 | length 86.1
  L1-TOP w6: U4.34@8086.24,4266.35 8086.24,4314.58 R21.1@8084.27,4316.55 C35.2@8119.31,4316.55
FT232_VCCD: C11.2 C15.2 C16.2 C17.2 C23.2 C28.2 C29.2 C33.2 C39.2 C41.2 C42.2 FB2.1 FB3.1 R21.2 R25.2 R28.2 U3.1 U3.5 U4.12 U4.24 U4.39 U4.46 U5.1 U5.5 U6.1 U7.1 U7.5 U20.8 | length 1226.5
  L1-TOP w6: R25.2@7729.94,3863.79 7727.97,3863.79 7702.38,3889.39 7702.38,3979.94 7727.97,4005.53 v2(7729.94,4005.53)
  L1-TOP w8: U20.8@7858.87,3840.17 7863.5,3835.55 7863.5,3787.94 7865.21,3786.24 7873.24,3786.24 C41.2@7868.13,3781.12 v2(7878.36,3781.12) ; C23.2@7867.73,4198.05 7920.29,4198.05 7942.93,4175.41 v2(7942.93,4174.82) 7944.54,4176.43 7996.32,4176.43 U4.39@7996.67,4176.79 ; v2(7950.8,4037.02) 7952.42,4038.64 7996.32,4038.64 U4.46@7996.67,4038.99 ; U4.12@8263.4,3949.42 8263.48,3949.35 8263.48,3882.22 v2(8265.37,3880.33) ; U4.24@8313.6,4216.16 8313.95,4216.51 8358.64,4216.51 v2(8359.86,4217.73) ; v2(8422.85,4265.76) 8424.03,4264.58 8474.82,4264.58 U7.1@8476,4263.4 8503.56,4263.4 8540.96,4226 U7.5@8582.3,4226 ; v2(8426.79,3852.77) 8428.16,3851.39 8474.62,3851.39 U5.1@8476,3850.02 8507.5,3850.02 8544.9,3812.61 U5.5@8582.3,3812.61 ; v2(8426.79,3990.57) 8428.16,3989.19 8474.62,3989.19 U6.1@8476,3987.81 ; v2(8426.79,4131.9) 8429.94,4128.76 8472.85,4128.76 U3.1@8476,4125.61 8511.43,4125.61 8548.83,4088.2 U3.5@8582.3,4088.2
  L1-TOP w10: v2(8107.89,3733.09) 8114.39,3733.09 8125.15,3743.85 C42.2@8154.6,3743.85 ; C42.2@8155.66,3743.85 8185.12,3743.85 8195.88,3733.09 v2(8202.38,3733.09)
  other v2: 8155.13,3743.32 8044.9,4316.55
FT232_VREGIN: C19.2 C22.2 FB4.1 U4.40 | length 97.1
  L1-TOP w8: v2(7942.93,4103.95) v2(7942.93,4139.39) ; C22.2@7942.93,4139.98 v2(7942.93,4139.39) ; U4.40@7996.67,4157.1 7975.94,4157.1 7958.23,4139.39 v2(7942.93,4139.39)
  other v2: 7863.01,4127.97 7863.01,4166.55
FTDI_TCK: U3.3 U4.13 | length 215.8
  L1-TOP w4.96: U4.13@8313.6,3999.62 8334.27,3999.62 8348.05,3985.84 8391.35,3985.84 8403.16,3997.65 8403.16,4033.09 8420.88,4050.8 U3.3@8476,4050.8
FTDI_TDI: U4.14 U5.3 | length 360.4
  L1-TOP w4.96: U4.14@8313.6,4019.31 8350.02,4019.31 v2(8359.86,4009.46) ; v2(8426.79,3777.18) 8474.03,3777.18 U5.3@8476,3775.21
  L10-BOT w4.96: v2(8359.86,4009.46) 8359.86,3844.11 v2(8426.79,3777.18)
FTDI_TDO: U4.15 U6.3 | length 251.5
  L1-TOP w4.96: U4.15@8313.6,4038.99 8365.76,4038.99 v2(8379.54,4025.21) ; v2(8426.79,3914.98) 8474.03,3914.98 U6.3@8476,3913.01
  L10-BOT w4.96: v2(8379.54,4025.21) 8379.54,3962.22 v2(8426.79,3914.98)
FTDI_TMS: U4.16 U7.3 | length 269.3
  L1-TOP w4.96: U4.16@8313.6,4058.68 8353.95,4058.68 8362.28,4067 8362.28,4122.12 8375.61,4135.45 8391.35,4135.45 8399.23,4143.32 8399.23,4178.76 8409.07,4188.6 U7.3@8476,4188.6
GIGE_INT_B: MC1.91 R114.1 U18.60 | length 691.9
  L1-TOP w7: MC1.91@4064.96,4511.42 4064.96,4547.98 4115.92,4598.94 4488.7,4598.94 4507.87,4618.11 4507.87,4643.7 4482.28,4669.29 v1(4480.31,4669.29) 4480.31,4692.09 4441.54,4730.87 U18.60@4441.54,4772.87
GIGE_LED_MODE: MC1.94 R183.1 R184.2 | length 994.3
  L1-TOP w5: R184.2@4574.8,4622.05 v1(4574.8,4657.48)
  L8-SIG w6: v1(4084.65,4302.11) 4043.31,4343.45 4043.31,4641.73 4136.45,4734.88 4497.41,4734.88 v1(4574.8,4657.48)
GIGE_MDC: MC1.102 R116.1 U18.20 | length 1685
  L1-TOP w4.55: U18.20@4461.23,5221.69 4461.23,5360.83 4470.78,5370.39 4470.78,5372.35 4478.35,5379.92 v1(4480.31,5379.92)
  L10-BOT w4.55: v1(4163.39,4302.11) 4175.11,4302.11 4200,4327 4200,4413 4244,4457 4244,4551.1 4229,4566.1 4229,4586.39 4237.44,4594.83 4503.77,4594.83 4530.46,4621.52 4530.46,4660.89 4609.2,4739.63 4609.2,5296.31 4525.59,5379.92 v1(4480.31,5379.92)
GIGE_MDIO: MC1.100 R115.1 U18.21 | length 1769
  L1-TOP w4.55: v1(4127.84,4340.27) 4143.7,4324.41 MC1.100@4143.7,4268.11 ; v1(4440.94,5379.92) 4441.54,5379.32 U18.21@4441.54,5221.69
  L10-BOT w4.55: v1(4127.84,4340.27) 4141.27,4340.27 4161,4360 4161,4421 4144,4438 4144,4494 4163,4513 4181,4513 4203,4535 4203,4580.95 4227.65,4605.6 4499.3,4605.6 4519.69,4625.98 4519.69,4665.35 4598.43,4744.09 4598.43,5291.34 4526.51,5363.25 4457.62,5363.25 v1(4440.94,5379.92)
GIGE_RESET_B: D3.2 MC1.92 R119.1 | length 1542.4
  L1-TOP w4.05: D3.2@4984.25,4710.77 v1(4985.77,4709.25)
  L1-TOP w5: D3.2@4984.25,4710.77 R119.1@4984.25,4771.65
  L8-SIG w6: v1(4064.96,4234.11) 4029.77,4269.3 4029.77,4695.12 4094.49,4759.84 4602.36,4759.84 4641.73,4720.47 4974.55,4720.47 v1(4985.77,4709.25)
